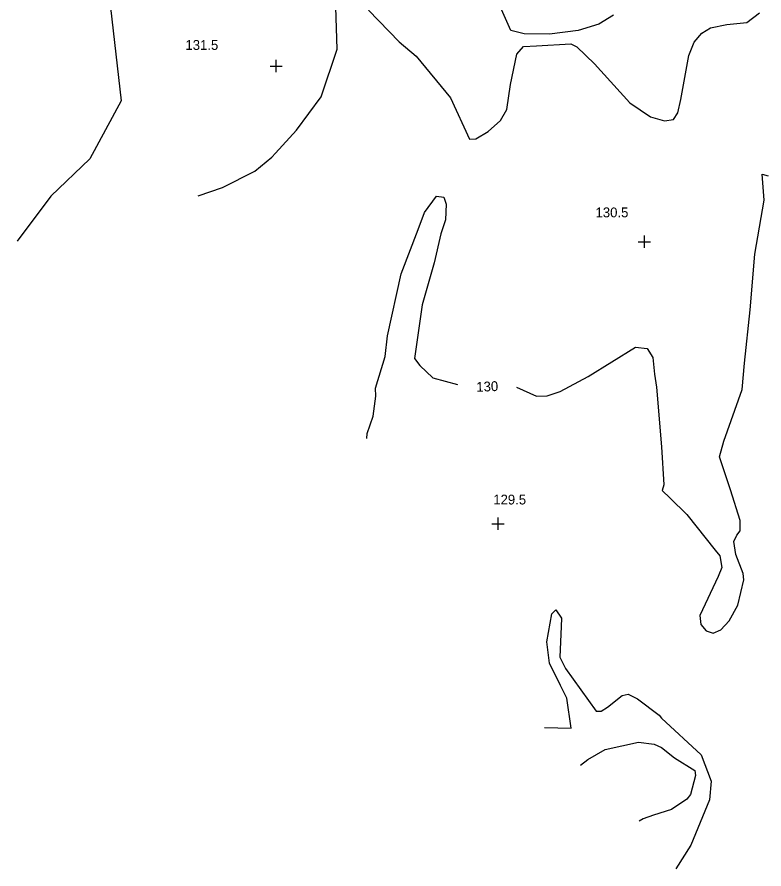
# Model space of a CAD drawing. Extents: x 1475150 to 2003689, y 770235 to 1112803.
# Drawn here: x 2000897.2 to 2001049.4, y 772747.2 to 772920.8 of the extents above; entities that cross this region are included whole.
import ezdxf

# ---------------------------------------------------------------- set-up
doc = ezdxf.new("R2010")
doc.units = 0
for name, color, linetype in [('RD_DTM_Major1', 7, 'Continuous'), ('RD_DTM_Major1_Lbl', 7, 'Continuous'), ('RD_DTM_Minor1', 7, 'Continuous'), ('RD_DTM_Obscure', 7, 'Continuous'), ('RD_DTM_Spot_Elev', 7, 'Continuous')]:
    doc.layers.add(name, color=color, linetype=linetype)

msp = doc.modelspace()

# ---------------------------------------------------------------- linework, layer by layer
at = {"layer": 'RD_DTM_Major1'}
for points in [[(2000998.96, 772845.35), (2001002.99, 772843.52), (2001005.2, 772843.63), (2001007.86, 772844.48), (2001013.57, 772847.53), (2001023.21, 772853.49), (2001025.55, 772853.25), (2001026.7, 772851.44), (2001027.04, 772848.01), (2001027.49, 772845.39), (2001028.51, 772833.25), (2001028.96, 772825.49), (2001028.59, 772824.31), (2001030.22, 772822.79), (2001033.62, 772819.43), (2001039.42, 772812.17), (2001040.39, 772811.04), (2001040.75, 772808.62), (2001040.05, 772806.78), (2001036.26, 772798.84), (2001036.53, 772797.03), (2001037.6, 772795.76), (2001039.01, 772795.29), (2001040.6, 772795.93), (2001042.25, 772797.75), (2001044.02, 772800.98), (2001045.27, 772806.15), (2001045.15, 772807.44), (2001043.6, 772811.26), (2001043.24, 772813.96), (2001043.83, 772815.25), (2001044.49, 772816.14), (2001044.52, 772818.24), (2001042.53, 772824.44), (2001040.29, 772831.16), (2001041.17, 772834.34), (2001044.95, 772844.87), (2001045.37, 772850.24), (2001046.52, 772861.14), (2001047.51, 772872.48), (2001049.43, 772883.45), (2001048.97, 772888.75), (2001050.2, 772888.45)], [(2000968.44, 772834.93), (2000968.44, 772834.94), (2000968.51, 772835.94), (2000969.76, 772839.49), (2000970.28, 772843.51), (2000970.24, 772845.18), (2000972.19, 772851.59), (2000972.62, 772855.82), (2000975.41, 772868.45), (2000978.91, 772877.46), (2000980.16, 772880.96), (2000982.67, 772884.28), (2000984.11, 772884.09), (2000984.59, 772882.63), (2000984.45, 772879.43), (2000983.54, 772876.61), (2000982.16, 772870.71), (2000979.69, 772862.12), (2000978.17, 772851.21), (2000979.21, 772849.79), (2000981.86, 772847.26), (2000986.92, 772845.92)]]:
    msp.add_lwpolyline(points, dxfattribs=at)
at = {"layer": 'RD_DTM_Minor1'}
for points in [[(2000934.1, 772884.33), (2000939.05, 772886.07), (2000945.63, 772889.4), (2000949.11, 772892.21), (2000949.8, 772893.01), (2000954.14, 772897.73), (2000959.15, 772904.48), (2000962.4, 772914.24), (2000962.15, 772922.75)], [(2000968.77, 772922.17), (2000975.05, 772915.71), (2000978.47, 772912.79), (2000985.47, 772904.32), (2000989.36, 772895.88), (2000990.67, 772895.94), (2000993.18, 772897.47), (2000995.66, 772899.71), (2000996.94, 772901.91), (2000997.74, 772906.99), (2000998.98, 772913.19), (2001000.33, 772914.78), (2001003, 772914.92), (2001009.98, 772915.31), (2001011.21, 772914.71), (2001014.82, 772911.21), (2001022.05, 772903.28), (2001026.22, 772900.45), (2001029.12, 772899.61), (2001030.92, 772899.88), (2001031.82, 772901.24), (2001032.39, 772903.97), (2001034.05, 772912.94), (2001035.17, 772915.64), (2001036.69, 772917.48), (2001038.45, 772918.55), (2001041.78, 772919.24), (2001045.89, 772919.63), (2001048.45, 772921.6)], [(2001018.69, 772921.11), (2001015.68, 772919.29), (2001011.47, 772918.02), (2001005.63, 772917.28), (2001000.49, 772917.33), (2000997.78, 772917.99), (2000995.86, 772922.31)], [(2001004.62, 772776.02), (2001010.06, 772775.92), (2001009.2, 772782.05), (2001007.93, 772784.63), (2001005.63, 772789.13), (2001005.1, 772793.49), (2001006.16, 772799.22), (2001006.98, 772800.05), (2001008.08, 772798.35), (2001008.03, 772796.64), (2001007.77, 772790.35), (2001008.94, 772788.06), (2001015.14, 772779.41), (2001016.16, 772779.37), (2001017.5, 772780.17), (2001020.48, 772782.59), (2001021.72, 772782.82), (2001023.59, 772781.87), (2001028.03, 772778.57), (2001028.48, 772777.98), (2001036.58, 772770.51), (2001038.63, 772765.12), (2001038.26, 772761.35), (2001034.47, 772752.05), (2001031.37, 772747.24)], [(2001012, 772768.39), (2001013.49, 772769.54), (2001017.03, 772771.57), (2001023.81, 772773.03), (2001027, 772772.69), (2001028.46, 772772.01), (2001031.16, 772769.87), (2001035.26, 772767.3), (2001035.41, 772766.28), (2001034.37, 772762.37), (2001033.64, 772761.46), (2001030.54, 772759.37), (2001026.88, 772758.21), (2001024.72, 772757.47), (2001023.93, 772756.98)]]:
    msp.add_lwpolyline(points, dxfattribs=at)
at = {"layer": 'RD_DTM_Obscure'}
msp.add_lwpolyline([(2000916.21, 772922.72), (2000918.39, 772903.69), (2000912.02, 772891.85), (2000904.02, 772884.25), (2000897.17, 772875.09)], dxfattribs=at)
at = {"layer": 'RD_DTM_Spot_Elev'}
for p, q in [((2000948.72, 772910.77), (2000951.22, 772910.77)), ((2000949.97, 772909.52), (2000949.97, 772912.02)), ((2001025, 772873.75), (2001025, 772876.25)), ((2001023.75, 772875), (2001026.25, 772875)), ((2000995.18, 772816.31), (2000995.18, 772818.81)), ((2000993.93, 772817.56), (2000996.43, 772817.56))]:
    msp.add_line(p, q, dxfattribs=at)

# ---------------------------------------------------------------- texts
at = {"layer": 'RD_DTM_Major1_Lbl'}
msp.add_text('130', height=2, rotation=2.554, dxfattribs=at).set_placement((2000990.79, 772844.41))
at = {"layer": 'RD_DTM_Spot_Elev'}
for s, p in [('131.5', (2000931.48, 772914.07)), ('130.5', (2001015.04, 772879.97)), ('129.5', (2000994.2, 772821.48))]:
    msp.add_text(s, height=2, dxfattribs=at).set_placement(p)

doc.saveas('drawing.dxf')
